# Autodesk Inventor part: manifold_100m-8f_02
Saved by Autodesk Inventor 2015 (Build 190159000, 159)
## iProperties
Created: 2021-02
Part Number: manifold_100m-8f_02
Checked By: TraceParts S.A.
Material: Generic
Catalog Web Link: www.traceparts.com
Document SubType Name: Modeling
Designer: TraceParts
Density: 1 g/cm^3
Appearance: Default
Company: TraceParts S.A.
Author: TraceParts
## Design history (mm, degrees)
feature "manifold_100m-8f_02.ipt"
body "Solid1"
